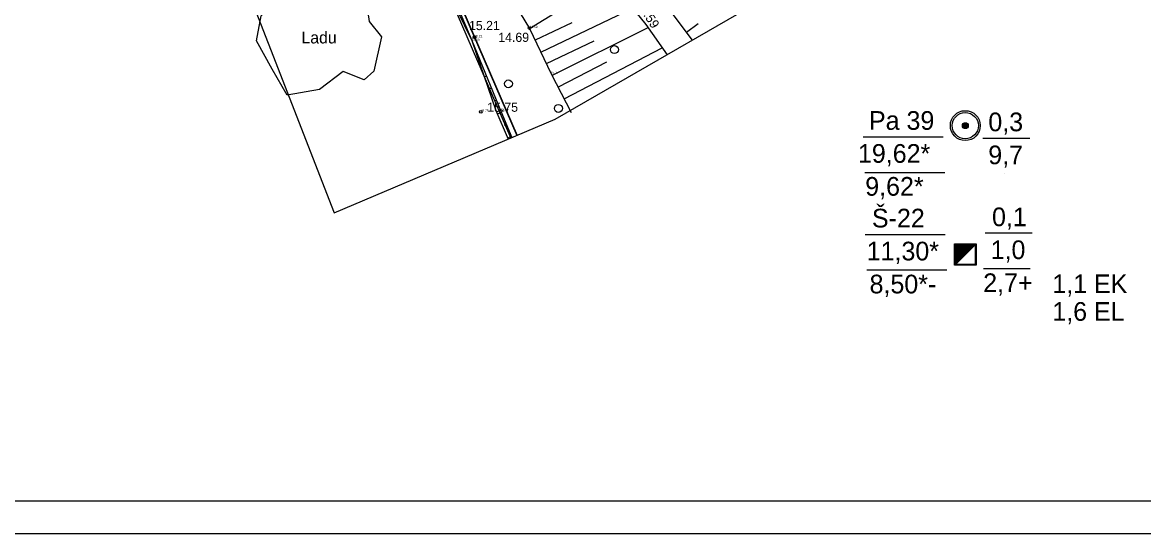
# Model space of a CAD drawing. Extents: x 433497 to 434382, y 6534486 to 6534993.
# Drawn here: x 433583 to 433753.8, y 6534486 to 6534564 of the extents above; entities that cross this region are included whole.
import ezdxf

# ---------------------------------------------------------------- set-up
doc = ezdxf.new("R2010")
doc.units = 0
for name, color, linetype in [('HALJASTUS', 7, 'Continuous'), ('kataster', 7, 'Continuous'), ('KORGUS-EH2000', 7, 'Continuous'), ('MOOTKORG-EH2000', 7, 'Continuous'), ('PIIR', 7, 'Continuous'), ('RELJEEF', 7, 'Continuous'), ('VORMISTUS', 7, 'Continuous')]:
    doc.layers.add(name, color=color, linetype=linetype)

msp = doc.modelspace()

# ---------------------------------------------------------------- linework, layer by layer
at = {"layer": 'HALJASTUS'}
for centre in [(433673.17, 6534559.86), (433657.02, 6534554.64), (433664.63, 6534550.88)]:
    msp.add_circle(centre, 0.6, dxfattribs=at)
at = {"layer": 'kataster'}
for points in [[(433658.34, 6534546.76), (433632.77, 6534606.03), (433617.1, 6534791), (433580.11, 6534776.84)], [(433633.5, 6534604.33), (433658.34, 6534546.76)]]:
    msp.add_lwpolyline(points, dxfattribs=at)
at = {"layer": 'KORGUS-EH2000'}
for centre in [(433660.23, 6534563.14), (433651.83, 6534561.74), (433652.79, 6534550.37)]:
    msp.add_circle(centre, 0.2, dxfattribs=at)
at = {"layer": 'PIIR'}
for points in [[(433632.2, 6534604.67), (433657.36, 6534546.35)], [(433633.45, 6534604.3), (433658.28, 6534546.74)]]:
    msp.add_lwpolyline(points, dxfattribs=at)
at = {"layer": 'RELJEEF'}
for p, q in [((433660.21, 6534563.09), (433666.94, 6534567.18)), ((433661.93, 6534559.48), (433675.96, 6534566.16)), ((433650.55, 6534563.2), (433650.6, 6534563.23)), ((433666.66, 6534563.95), (433661.07, 6534561.29)), ((433663.65, 6534555.88), (433678.3, 6534563.21)), ((433685.94, 6534563.81), (433684.16, 6534562.46)), ((433651.38, 6534561.38), (433651.37, 6534561.38)), ((433652.09, 6534559.51), (433652.14, 6534559.53)), ((433670.01, 6534561.14), (433662.79, 6534557.68)), ((433665.5, 6534552.33), (433680.46, 6534560.1)), ((433671.94, 6534557.93), (433664.58, 6534554.1)), ((433652.89, 6534557.68), (433652.68, 6534557.59)), ((433653.49, 6534555.76), (433653.65, 6534555.83)), ((433654.41, 6534553.98), (433653.98, 6534553.8)), ((433654.9, 6534552.02), (433655.17, 6534552.13)), ((433655.93, 6534550.28), (433655.32, 6534550.03)), ((433656.41, 6534548.31), (433656.71, 6534548.44)), ((433657.48, 6534546.59), (433656.92, 6534546.36))]:
    msp.add_line(p, q, dxfattribs=at)
for points in [[(433635.05, 6534602.21), (433637.8, 6534596.33), (433640.54, 6534587.76), (433644.38, 6534578.11), (433647.43, 6534570.78), (433651.44, 6534561.24), (433655.86, 6534550.45), (433657.55, 6534546.43)], [(433634.11, 6534601.8), (433636.89, 6534594.67), (433639.89, 6534587.61), (433643.8, 6534577.9), (433646.82, 6534570.73), (433651.44, 6534561.24), (433655.08, 6534550.57), (433656.99, 6534546.19)], [(433642.77, 6534601.4), (433644.81, 6534593.05), (433651.27, 6534577.82), (433660.21, 6534563.09)], [(433642.77, 6534601.4), (433644.81, 6534593.05), (433651.27, 6534577.82), (433660.21, 6534563.09)], [(433658.05, 6534599), (433658.87, 6534598.97), (433660.05, 6534598.63), (433661.03, 6534598.18), (433661.46, 6534597.32), (433664.34, 6534589.99), (433667.65, 6534583.28), (433671.26, 6534577.69), (433675.43, 6534572.69), (433677.42, 6534570.38), (433681.63, 6534565.8), (433685.04, 6534561.3)], [(433633.6, 6534570.9), (433635.14, 6534568.68), (433635.8, 6534564.14), (433637.67, 6534561.8), (433636.5, 6534556.58), (433635.04, 6534555.26), (433631.85, 6534556.53), (433628.21, 6534553.78), (433623.31, 6534552.93), (433620.99, 6534556.89), (433618.63, 6534561.2), (433619.35, 6534564.99), (433622.46, 6534568), (433626, 6534569.99), (433629.94, 6534570.51), (433633.6, 6534570.9)], [(433675.76, 6534566.4), (433677.96, 6534563.69), (433681.18, 6534559.07)], [(433660.19, 6534563.12), (433660.21, 6534563.09), (433663.52, 6534556.14), (433666.57, 6534550.26)]]:
    msp.add_lwpolyline(points, dxfattribs=at)
at = {"layer": 'VORMISTUS'}
for p, q in [((433725.15, 6534527.1), (433728.15, 6534530.1)), ((433725.15, 6534527.13), (433728.12, 6534530.1)), ((433725.15, 6534527.2), (433728.05, 6534530.1)), ((433725.15, 6534527.27), (433727.98, 6534530.1)), ((433725.15, 6534527.34), (433727.91, 6534530.1)), ((433725.15, 6534527.41), (433727.84, 6534530.1)), ((433725.15, 6534527.48), (433727.77, 6534530.1)), ((433725.15, 6534527.55), (433727.69, 6534530.1)), ((433725.15, 6534527.62), (433727.62, 6534530.1)), ((433725.15, 6534527.7), (433727.55, 6534530.1)), ((433725.15, 6534527.77), (433727.48, 6534530.1)), ((433725.15, 6534527.84), (433727.41, 6534530.1)), ((433725.15, 6534527.91), (433727.34, 6534530.1)), ((433725.15, 6534527.98), (433727.27, 6534530.1)), ((433725.15, 6534528.05), (433727.2, 6534530.1)), ((433725.15, 6534528.12), (433727.13, 6534530.1)), ((433725.15, 6534528.19), (433727.06, 6534530.1)), ((433725.15, 6534528.26), (433726.99, 6534530.1)), ((433725.15, 6534528.33), (433726.92, 6534530.1)), ((433725.15, 6534528.4), (433726.85, 6534530.1)), ((433725.15, 6534528.47), (433726.78, 6534530.1)), ((433725.15, 6534528.54), (433726.7, 6534530.1)), ((433725.15, 6534528.61), (433726.63, 6534530.1)), ((433725.15, 6534528.69), (433726.56, 6534530.1)), ((433725.15, 6534528.76), (433726.49, 6534530.1)), ((433725.15, 6534528.83), (433726.42, 6534530.1)), ((433725.15, 6534528.9), (433726.35, 6534530.1)), ((433725.15, 6534528.97), (433726.28, 6534530.1)), ((433725.15, 6534529.04), (433726.21, 6534530.1)), ((433725.15, 6534529.11), (433726.14, 6534530.1)), ((433725.15, 6534529.18), (433726.07, 6534530.1)), ((433725.15, 6534529.25), (433726, 6534530.1)), ((433725.15, 6534529.32), (433725.93, 6534530.1)), ((433725.15, 6534529.39), (433725.86, 6534530.1)), ((433725.15, 6534529.46), (433725.79, 6534530.1)), ((433725.15, 6534529.53), (433725.71, 6534530.1)), ((433725.15, 6534529.6), (433725.64, 6534530.1)), ((433725.15, 6534529.68), (433725.57, 6534530.1)), ((433725.15, 6534529.75), (433725.5, 6534530.1)), ((433725.15, 6534529.82), (433725.43, 6534530.1)), ((433725.15, 6534529.89), (433725.36, 6534530.1)), ((433725.15, 6534529.96), (433725.29, 6534530.1)), ((433725.15, 6534530.03), (433725.22, 6534530.1))]:
    msp.add_line(p, q, dxfattribs=at)
for points in [[(433496.62, 6534983.07), (433496.62, 6534486.03), (434381.62, 6534486.03), (434381.62, 6534983.07)], [(434376.62, 6534978.07), (433516.62, 6534978.07), (433516.62, 6534491.03), (434376.62, 6534491.03)], [(433725.01, 6534530.24), (433728.29, 6534530.24), (433728.29, 6534526.96), (433725.01, 6534526.96)], [(433725.15, 6534530.1), (433728.15, 6534530.1), (433728.15, 6534527.1), (433725.15, 6534527.1)]]:
    msp.add_lwpolyline(points, close=True, dxfattribs=at)
for points in [[(433756.83, 6534894.35), (433691.2, 6534872.09), (433653.51, 6534864.19), (433636.55, 6534862.39), (433627.67, 6534847.82), (433564.13, 6534829.69), (433582.61, 6534768.48), (433587.88, 6534751), (433591.76, 6534747.47), (433594.1, 6534737.42), (433589.97, 6534732.12), (433592.57, 6534706.45), (433596.13, 6534671.3), (433599.93, 6534613.56), (433630.45, 6534534.94), (433664.15, 6534549.23), (433704.54, 6534572.57), (433752.08, 6534596.22), (433789.5, 6534614.84)], [(433756.83, 6534894.35), (433691.2, 6534872.09), (433653.51, 6534864.19), (433636.55, 6534862.39), (433627.67, 6534847.82), (433564.13, 6534829.69), (433582.61, 6534768.48), (433587.88, 6534751), (433591.76, 6534747.47), (433594.1, 6534737.42), (433589.97, 6534732.12), (433592.57, 6534706.45), (433596.13, 6534671.3), (433599.93, 6534613.56), (433630.45, 6534534.94), (433664.15, 6534549.23), (433704.54, 6534572.57), (433752.08, 6534596.22), (433789.5, 6534614.84)], [(433711.09, 6534546.56), (433723.26, 6534546.56)], [(433736.46, 6534546.32), (433729.31, 6534546.32)], [(433711.35, 6534541.13), (433723.53, 6534541.13)], [(433732.62, 6534540.9), (433732.62, 6534540.9)], [(433711.37, 6534531.66), (433723.55, 6534531.66)], [(433736.81, 6534531.84), (433729.66, 6534531.84)], [(433711.63, 6534526.24), (433723.81, 6534526.24)], [(433736.54, 6534526.43), (433729.4, 6534526.43)], [(433736.54, 6534526.43), (433729.4, 6534526.43)]]:
    msp.add_lwpolyline(points, dxfattribs=at)
for radius in [2.28, 2, 0.45, 0.4, 0.35, 0.3, 0.25, 0.2, 0.15, 0.1, 0.05]:
    msp.add_circle((433726.64, 6534548.26), radius, dxfattribs=at)

# ---------------------------------------------------------------- texts
at = {"layer": 'KORGUS-EH2000'}
msp.add_text('12.59', height=1.4, rotation=302.6194, dxfattribs=at).set_placement((433676.41, 6534566.88))
for s, p in [('15.21', (433651.01, 6534562.83)), ('14.69', (433655.47, 6534561.03)), ('15.75', (433653.79, 6534550.37))]:
    msp.add_text(s, height=1.4, dxfattribs=at).set_placement(p)
at = {"layer": 'MOOTKORG-EH2000'}
for s, p in [('14.69', (433660.23, 6534563.14)), ('15.26', (433651.44, 6534561.24)), ('15.21', (433651.83, 6534561.74)), ('15.37', (433663.45, 6534556.16)), ('15.73', (433655.08, 6534550.57)), ('15.75', (433652.79, 6534550.37)), ('15.87', (433655.86, 6534550.45))]:
    msp.add_text(s, height=0.35, dxfattribs=at).set_placement(p)
at = {"layer": 'RELJEEF'}
msp.add_text('Ladu', height=1.8, dxfattribs=at).set_placement((433625.48, 6534560.79))
at = {"layer": 'VORMISTUS'}
for s, p in [('Pa 39', (433711.96, 6534547.62)), ('0,3', (433730.15, 6534547.4)), ('19,62*', (433710.28, 6534542.59)), ('9,7', (433730.14, 6534542.37)), ('9,62*', (433711.39, 6534537.57)), ('Š-22', (433712.41, 6534532.73)), ('0,1', (433730.71, 6534532.92)), ('11,30*', (433711.61, 6534527.7)), ('1,0', (433730.5, 6534527.9)), ('8,50*-', (433712.05, 6534522.67)), ('2,7+', (433729.37, 6534522.87)), ('1,1 EK', (433739.9, 6534522.71)), ('1,6 EL', (433739.9, 6534518.49))]:
    msp.add_text(s, height=2.85, dxfattribs=at).set_placement(p)

doc.saveas('drawing.dxf')
